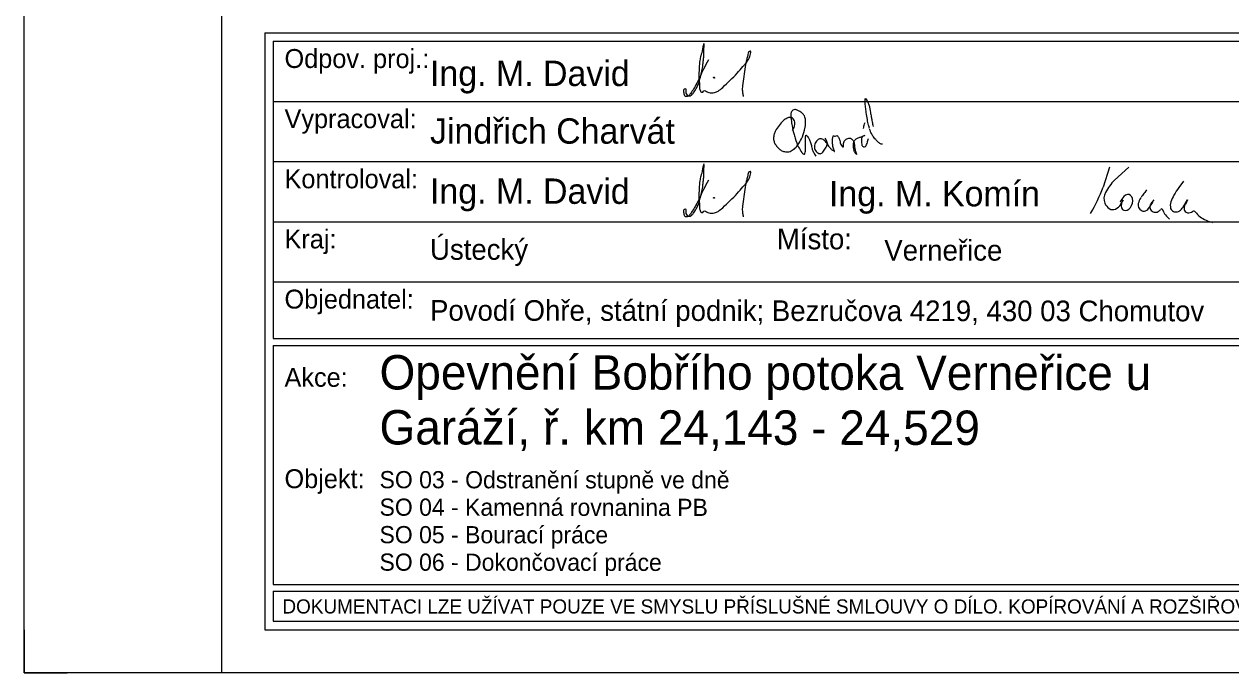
# Model space of a CAD drawing. Extents: x 67.3 to 115.4, y -93.9 to -78.3.
# Drawn here: x 104.8 to 111.82, y -93.93 to -90.16 of the extents above; entities that cross this region are included whole.
import ezdxf

# ---------------------------------------------------------------- set-up
doc = ezdxf.new("R2010")
doc.units = 0
for name, color, linetype in [('07_rozpiska', 7, 'Continuous'), ('07_rámeček', 7, 'Continuous'), ('Default', 7, 'Continuous'), ('Rozpiska + rámeček', 7, 'Continuous')]:
    doc.layers.add(name, color=color, linetype=linetype)

# ---------------------------------------------------------------- blocks, each defined once
blk = doc.blocks.new('Charvat')
at = {"layer": 'Rozpiska + rámeček'}
for points in [[(0.0826, 0.02), (0.0817, 0.0228), (0.0806, 0.0281), (0.0796, 0.0345), (0.0789, 0.0395), (0.0784, 0.0445), (0.0784, 0.0456), (0.0785, 0.0469), (0.0787, 0.0476), (0.0791, 0.0473), (0.0804, 0.0456), (0.0816, 0.0427), (0.0827, 0.0394), (0.0832, 0.0363), (0.0841, 0.0314), (0.0846, 0.0282), (0.0855, 0.0238), (0.086, 0.0216)], [(0.0108, 0.0178), (0.0123, 0.0208), (0.0129, 0.0234), (0.0122, 0.0279), (0.0108, 0.0294), (0.0087, 0.0301), (0.0059, 0.0293), (0.0024, 0.0271), (-0.0017, 0.0225), (-0.0049, 0.0177), (-0.0062, 0.0145), (-0.0067, 0.0115), (-0.0063, 0.0075), (-0.0059, 0.0064), (-0.0039, 0.0034), (-0.0014, 0.0007), (0.001, -0.001), (0.0043, -0.0019), (0.0075, -0.0019), (0.0097, -0.001), (0.0131, 0.0013), (0.0158, 0.0045), (0.0192, 0.0101), (0.022, 0.0182), (0.0223, 0.0193), (0.023, 0.0256), (0.0227, 0.0293), (0.0219, 0.0315), (0.0199, 0.034), (0.017, 0.036), (0.0147, 0.0371), (0.0142, 0.0372), (0.013, 0.0373), (0.0113, 0.0368), (0.0106, 0.0362), (0.0097, 0.0348), (0.0095, 0.0343), (0.0093, 0.0333), (0.0093, 0.0314), (0.0096, 0.0279), (0.0105, 0.0221), (0.012, 0.0151), (0.0133, 0.0108), (0.0166, 0.0023), (0.0195, -0.0026), (0.0202, -0.0035), (0.0214, -0.0042), (0.022, -0.0042), (0.0225, -0.0034), (0.023, -0.0014), (0.0231, 0), (0.0231, 0.0051), (0.0231, 0.0111), (0.0231, 0.0124), (0.0233, 0.0132), (0.0236, 0.0135), (0.024, 0.0133), (0.0254, 0.0115), (0.0268, 0.0092), (0.0279, 0.0059), (0.0289, 0.0018), (0.0298, -0.0012), (0.0315, -0.0041), (0.0327, -0.0059)], [(0.0771, 0.0198), (0.0779, 0.024), (0.0784, 0.0252)], [(0.0428, 0.0062), (0.0417, 0.0075), (0.0401, 0.009), (0.0394, 0.0095), (0.0378, 0.0101), (0.0368, 0.0101), (0.0353, 0.0098), (0.034, 0.0088), (0.0326, 0.0071), (0.0316, 0.0051), (0.0313, 0.0026), (0.0313, 0.0011), (0.0322, -0.0007), (0.0338, -0.0025), (0.0354, -0.0034), (0.0366, -0.0037), (0.0381, -0.0031), (0.0397, -0.0014), (0.0411, 0.0004), (0.0422, 0.0025), (0.043, 0.005), (0.043, 0.0063), (0.0429, 0.0069), (0.0424, 0.0086), (0.0414, 0.0106), (0.0421, 0.009), (0.0433, 0.0053), (0.0444, 0.0034), (0.0458, 0.0017), (0.0476, 0), (0.0497, -0.0015), (0.0498, -0.0016), (0.0499, -0.0016), (0.0499, -0.0014), (0.0492, 0.0003), (0.0487, 0.0022), (0.0482, 0.0055), (0.048, 0.0086), (0.0484, 0.0114), (0.0491, 0.0131), (0.0493, 0.013), (0.0506, 0.0127), (0.0522, 0.0131), (0.0539, 0.0111), (0.0547, 0.0094), (0.0552, 0.0074), (0.0556, 0.0056), (0.0566, 0.0038), (0.058, 0.0025), (0.0582, 0.0031), (0.0585, 0.0057), (0.0589, 0.0076), (0.0593, 0.0083), (0.0604, 0.0095), (0.0616, 0.0102), (0.0632, 0.0106), (0.065, 0.0106), (0.0665, 0.0094), (0.0678, 0.0078), (0.0686, 0.0033), (0.0691, 0.0001), (0.0701, -0.0031), (0.0705, -0.0044), (0.0697, -0.0035), (0.0682, -0.0005), (0.0677, 0.0025), (0.0677, 0.0059), (0.0683, 0.0079), (0.0702, 0.01), (0.0728, 0.0114), (0.0756, 0.0122), (0.0781, 0.0133), (0.0764, 0.0125), (0.0755, 0.0112), (0.0751, 0.0096), (0.0751, 0.0075), (0.0753, 0.005), (0.0753, 0.0048), (0.0758, 0.0038), (0.0766, 0.003), (0.0772, 0.0026), (0.0776, 0.0025), (0.0783, 0.0027), (0.0791, 0.0034), (0.0799, 0.0047), (0.0806, 0.0069), (0.0816, 0.0104)], [(0.0947, 0.0053), (0.0934, 0.0053), (0.0921, 0.0059), (0.0901, 0.0076), (0.0883, 0.0095), (0.0858, 0.0127), (0.0839, 0.0159), (0.0829, 0.0186), (0.0827, 0.0193)]]:
    blk.add_spline(points, degree=3, dxfattribs=at)

msp = doc.modelspace()

# ---------------------------------------------------------------- linework, layer by layer
at = {"layer": '07_rozpiska'}
for points in [[(108.7509, -90.2979), (108.7522, -90.2881), (108.7515, -90.2684), (108.7437, -90.2992), (108.7334, -90.3413), (108.7272, -90.3675), (108.724, -90.4112), (108.7224, -90.4469), (108.7256, -90.5214), (108.7288, -90.5411), (108.7415, -90.5528), (108.746, -90.5496), (108.747, -90.5473), (108.7541, -90.5424), (108.7667, -90.5489), (108.7804, -90.5544), (108.7953, -90.557), (108.8134, -90.5541), (108.8338, -90.5457), (108.8604, -90.5243), (108.9041, -90.4832), (108.9443, -90.442), (108.9783, -90.4035), (109.0058, -90.3701), (109.0207, -90.3371), (109.0243, -90.3209), (109.023, -90.3141), (109.0168, -90.3154), (109.0061, -90.3387), (109.0003, -90.3626), (108.9916, -90.4044), (108.9828, -90.4601), (108.9757, -90.5162), (108.975, -90.545), (108.9786, -90.5667), (108.9805, -90.5774)], [(108.7447, -90.4031), (108.7467, -90.3772), (108.7493, -90.3546), (108.7512, -90.3303), (108.7509, -90.2979)], [(108.7771, -90.3636), (108.7496, -90.4184), (108.7033, -90.5104), (108.6699, -90.5648), (108.6576, -90.5761), (108.6482, -90.5777), (108.6424, -90.5771), (108.6381, -90.5703), (108.6362, -90.5583)], [(108.6362, -90.5583), (108.6343, -90.5466), (108.6352, -90.5389), (108.6401, -90.5324), (108.6437, -90.5317), (108.6456, -90.5437), (108.6462, -90.558), (108.6543, -90.5703), (108.6657, -90.5745), (108.6764, -90.5706), (108.6858, -90.5628), (108.6909, -90.556), (108.7062, -90.5317), (108.7123, -90.5201), (108.7282, -90.4738), (108.7447, -90.4031)], [(108.8095, -90.4653), (108.8072, -90.4663), (108.8072, -90.4683), (108.8089, -90.4692), (108.8121, -90.4699), (108.8127, -90.4683), (108.8127, -90.4666), (108.8095, -90.4653)], [(108.7509, -90.9979), (108.7522, -90.9881), (108.7515, -90.9684), (108.7437, -90.9992), (108.7334, -91.0413), (108.7272, -91.0675), (108.724, -91.1112), (108.7224, -91.1469), (108.7256, -91.2214), (108.7288, -91.2411), (108.7415, -91.2528), (108.746, -91.2496), (108.747, -91.2473), (108.7541, -91.2424), (108.7667, -91.2489), (108.7804, -91.2544), (108.7953, -91.257), (108.8134, -91.2541), (108.8338, -91.2457), (108.8604, -91.2243), (108.9041, -91.1832), (108.9443, -91.142), (108.9783, -91.1035), (109.0058, -91.0701), (109.0207, -91.0371), (109.0243, -91.0209), (109.023, -91.0141), (109.0168, -91.0154), (109.0061, -91.0387), (109.0003, -91.0626), (108.9916, -91.1044), (108.9828, -91.1601), (108.9757, -91.2162), (108.975, -91.245), (108.9786, -91.2667), (108.9805, -91.2774)], [(108.7447, -91.1031), (108.7467, -91.0772), (108.7493, -91.0546), (108.7512, -91.0303), (108.7509, -90.9979)], [(108.7771, -91.0636), (108.7496, -91.1184), (108.7033, -91.2104), (108.6699, -91.2648), (108.6576, -91.2761), (108.6482, -91.2777), (108.6424, -91.2771), (108.6381, -91.2703), (108.6362, -91.2583)], [(108.6362, -91.2583), (108.6343, -91.2466), (108.6352, -91.2389), (108.6401, -91.2324), (108.6437, -91.2317), (108.6456, -91.2437), (108.6462, -91.258), (108.6543, -91.2703), (108.6657, -91.2745), (108.6764, -91.2706), (108.6858, -91.2628), (108.6909, -91.256), (108.7062, -91.2317), (108.7123, -91.2201), (108.7282, -91.1738), (108.7447, -91.1031)], [(108.8095, -91.1653), (108.8072, -91.1663), (108.8072, -91.1683), (108.8089, -91.1692), (108.8121, -91.1699), (108.8127, -91.1683), (108.8127, -91.1666), (108.8095, -91.1653)]]:
    msp.add_spline(points, degree=3, dxfattribs=at)
at = {"layer": 'Default'}
for p, q in [((111.1756, -91.2049), (111.19, -91.179)), ((111.4175, -91.2337), (111.4276, -91.251)), ((111.4492, -91.2798), (111.4607, -91.2913))]:
    msp.add_line(p, q, dxfattribs=at)
for points in [[(111.1108, -90.9889), (111.0748, -91.1041)], [(111.2231, -90.9889), (111.1396, -91.0638)], [(111.5428, -91.071), (111.514, -91.107)], [(111.3268, -91.1214), (111.3167, -91.1358)], [(111.298, -91.1617), (111.2951, -91.1646)], [(111.3484, -91.2049), (111.3484, -91.2078)], [(111.3628, -91.1905), (111.37, -91.179), (111.3599, -91.1905)], [(111.5399, -91.2222), (111.5644, -91.179), (111.5543, -91.2049)], [(111.3455, -91.2222), (111.3455, -91.2222)]]:
    msp.add_lwpolyline(points, dxfattribs=at)
for centre, radius, start, end in [((111.3996, -91.3056), 0.3545, 137.00062, 151.51062), ((110.1415, -90.7574), 0.9948, 329.80858, 339.56815), ((111.152, -91.1722), 0.0732, 150.83631, 201.23374), ((111.5385, -91.3186), 0.288, 140.57196, 146.46893), ((111.7457, -91.2927), 0.2956, 141.11668, 151.43002), ((111.1585, -91.1626), 0.083, 205.78195, 234.22418), ((111.1076, -91.1548), 0.0864, 295.93387, 323.63221), ((111.2528, -91.2204), 0.084, 133.12102, 160.6603), ((111.232, -91.2127), 0.0529, 142.82783, 193.29225), ((111.3837, -91.2272), 0.1085, 146.31446, 165.71836), ((111.0538, -91.0072), 0.288, 326.31446, 326.46946), ((111.1949, -91.1115), 0.1862, 320.58833, 335.16259), ((111.3742, -91.2192), 0.0288, 154.94151, 187.17365), ((111.4014, -91.229), 0.0576, 139.19606, 154.94016), ((111.5266, -91.2134), 0.0617, 158.78845, 195.14726), ((111.6674, -91.2521), 0.2075, 150.931, 162.8917), ((111.6118, -91.2367), 0.0677, 151.17648, 169.00349), ((111.1301, -91.199), 0.0369, 236.98468, 294.62862), ((111.17, -91.3162), 0.0864, 108.04736, 108.08265), ((111.3104, -91.2122), 0.0323, 245.35778, 276.92267), ((111.3034, -91.1981), 0.0475, 283.31943, 318.16716), ((111.3742, -91.2205), 0.0286, 186.45097, 212.31824), ((111.3775, -91.2186), 0.0324, 212.08411, 258.70933), ((111.3791, -91.215), 0.0362, 257.35338, 296.27075), ((111.3728, -91.2108), 0.043, 301.37529, 327.02531), ((111.4138, -91.2371), 0.00576, 26.63136, 150.41952), ((111.5051, -91.2135), 0.0864, 206.63144, 229.82938), ((111.4923, -91.2215), 0.0265, 197.61582, 249.38851), ((111.4988, -91.2028), 0.0463, 250.12564, 275.82035), ((111.4994, -91.214), 0.035, 276.59581, 304.89281), ((111.4576, -91.1655), 0.099, 308.6573, 325.5075), ((111.5748, -91.2279), 0.0297, 172.16185, 218.17447), ((111.5739, -91.2195), 0.0349, 229.93747, 256.22885), ((111.5701, -91.2079), 0.0458, 264.36538, 302.31991), ((111.6017, -91.2581), 0.0136, 38.96313, 121.674), ((111.7211, -91.1734), 0.1329, 214.99845, 231.36881), ((111.7576, -91.1078), 0.2073, 234.79421, 256.99308)]:
    msp.add_arc(centre, radius, start, end, dxfattribs=at)
for centre, major_axis, ratio, start_param, end_param in [((111.2115, -91.1946), (0.0152, 0.0459), 0.677007, 2.488228, 7.220838), ((111.3143, -91.2113), (-0.0357, 0.0109), 0.932374, 0, 1.363098)]:
    msp.add_ellipse(centre, major_axis=major_axis, ratio=ratio, start_param=start_param, end_param=end_param, dxfattribs=at)
at = {"layer": 'Rozpiska + rámeček'}
for p, q in [((106.1958, -90.2063), (106.1958, -93.6813)), ((106.1958, -90.2063), (114.7958, -90.2063)), ((106.2458, -90.2563), (106.2458, -91.9863)), ((106.2458, -90.2563), (111.9058, -90.2563)), ((106.2458, -90.6063), (111.9058, -90.6063)), ((106.2458, -90.9563), (111.9058, -90.9563)), ((106.2458, -91.3063), (111.9058, -91.3063)), ((106.2458, -91.6563), (111.9058, -91.6563)), ((106.2458, -91.9863), (111.9058, -91.9863)), ((106.2458, -92.0263), (111.9058, -92.0263)), ((106.2458, -92.0263), (106.2458, -93.4163)), ((106.2458, -93.4163), (111.9058, -93.4163)), ((106.2458, -93.4563), (114.7458, -93.4563)), ((106.2458, -93.4563), (106.2458, -93.6313)), ((106.2458, -93.6313), (114.7458, -93.6313)), ((106.1958, -93.6813), (114.7958, -93.6813))]:
    msp.add_line(p, q, dxfattribs=at)
for points in [[(104.7958, -79.0813), (115.2958, -79.0813), (115.2958, -93.9313), (104.7958, -93.9313)], [(105.9458, -86.5063), (115.0458, -86.5063), (115.0458, -93.9313), (105.9458, -93.9313)]]:
    msp.add_lwpolyline(points, close=True, dxfattribs=at)
msp.add_lwpolyline([(104.7958, -93.6813), (104.7958, -93.9313), (105.0458, -93.9313)], dxfattribs=at)

# ---------------------------------------------------------------- block references
at = {"layer": '07_rámeček', "xscale": 6.250000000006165, "yscale": 6.250000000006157, "rotation": 3.739011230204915e-09}
msp.add_blockref('Charvat', (109.1988, -90.887), dxfattribs=at)

# ---------------------------------------------------------------- texts
at = {"layer": '07_rozpiska'}
for s, height, p in [('Opevnění Bobřího potoka Verneřice u ', 0.2, (106.8638, -92.2822)), ('Garáží, ř. km 24,143 - 24,529', 0.2, (106.8636, -92.6022)), ('SO 03 - Odstranění stupně ve dně', 0.1, (106.8639, -92.8569)), ('SO 04 - Kamenná rovnanina PB', 0.1, (106.8638, -93.0169)), ('SO 05 - Bourací práce', 0.1, (106.8636, -93.1769)), ('SO 06 - Dokončovací práce', 0.1, (106.8635, -93.3369))]:
    msp.add_text(s, height=height, rotation=359.95393, dxfattribs=at).set_placement(p)
at = {"layer": 'Rozpiska + rámeček'}
for s, height, rotation, p in [('Odpov. proj.:', 0.11, 359.95393, (106.3108, -90.4113)), ('Ing. M. David', 0.147465, 359.95278, (107.1575, -90.5157)), ('Vypracoval:', 0.11, 359.95393, (106.3108, -90.7613)), ('Jindřich Charvát', 0.147465, 359.95278, (107.1575, -90.8513)), ('Kontroloval:', 0.11, 359.95393, (106.3108, -91.1113)), ('Ing. M. David', 0.147465, 359.95278, (107.1575, -91.2013)), ('Ing. M. Komín', 0.147465, 359.95278, (109.4792, -91.2157)), ('Kraj:', 0.11, 359.95393, (106.3108, -91.4613)), ('Místo:', 0.12, 359.95393, (109.1758, -91.4663)), ('Ústecký', 0.12, 359.95393, (107.1575, -91.5273)), ('Verneřice', 0.12, 359.95278, (109.8008, -91.5321)), ('Objednatel:', 0.11, 359.95393, (106.3108, -91.8113)), ('Povodí Ohře, státní podnik; Bezručova 4219, 430 03 Chomutov', 0.12, 359.95278, (107.1575, -91.8821)), ('Akce:', 0.11, 359.95393, (106.3108, -92.2663)), ('Objekt:', 0.11, 359.95393, (106.3108, -92.8564))]:
    msp.add_text(s, height=height, rotation=rotation, dxfattribs=at).set_placement(p)
msp.add_text('DOKUMENTACI LZE UŽÍVAT POUZE VE SMYSLU PŘÍSLUŠNÉ SMLOUVY O DÍLO. KOPÍROVÁNÍ A ROZŠIŘOVÁNÍ POUZE PO PŘEDCHOZÍM SOUHLASU  AZ CONSULT spol. s. r.o.', height=0.0822563, dxfattribs=at).set_placement((106.2988, -93.5859))

doc.saveas('drawing.dxf')
